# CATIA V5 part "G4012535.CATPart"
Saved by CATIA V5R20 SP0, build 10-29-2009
Part number: G4012535
Revision: 4
Definition: design
Nomenclature: G4012535
Source: made
Description: NOT SPECIFIED
Bounding box of the stored display mesh (mm): x 0 to 35, y -17.817 to 17.817, z -18 to 18
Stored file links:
  C:\Users\Raffaele\Desktop\3D X SITO CF\BOLEX\25-BUSH REF 401\G4012535.CATPart
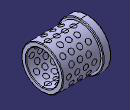
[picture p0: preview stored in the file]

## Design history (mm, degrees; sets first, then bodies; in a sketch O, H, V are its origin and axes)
Body1 "MANIFOLD_SOLID_BREP #8147" (main body)
  Solid1: solid without history
Body2 "MANIFOLD_SOLID_BREP #8294"
  Solid2: solid without history
Body3 "MANIFOLD_SOLID_BREP #8441"
  Solid3: solid without history
Body4 "MANIFOLD_SOLID_BREP #8588"
  Solid4: solid without history
Body5 "MANIFOLD_SOLID_BREP #8735"
  Solid5: solid without history
Body6 "MANIFOLD_SOLID_BREP #8884"
  Solid6: solid without history
Body7 "MANIFOLD_SOLID_BREP #9033"
  Solid7: solid without history
Body8 "MANIFOLD_SOLID_BREP #9182"
  Solid8: solid without history
Body9 "MANIFOLD_SOLID_BREP #9331"
  Solid9: solid without history
Body10 "MANIFOLD_SOLID_BREP #9480"
  Solid10: solid without history
Body11 "MANIFOLD_SOLID_BREP #9629"
  Solid11: solid without history
Body12 "MANIFOLD_SOLID_BREP #9778"
  Solid12: solid without history
Body13 "MANIFOLD_SOLID_BREP #9927"
  Solid13: solid without history
Body14 "MANIFOLD_SOLID_BREP #10076"
  Solid14: solid without history
Body15 "MANIFOLD_SOLID_BREP #10225"
  Solid15: solid without history
Body16 "MANIFOLD_SOLID_BREP #10374"
  Solid16: solid without history
Body17 "MANIFOLD_SOLID_BREP #10523"
  Solid17: solid without history
Body18 "MANIFOLD_SOLID_BREP #10672"
  Solid18: solid without history
Body19 "MANIFOLD_SOLID_BREP #10821"
  Solid19: solid without history
Body20 "MANIFOLD_SOLID_BREP #10972"
  Solid20: solid without history
Body21 "MANIFOLD_SOLID_BREP #11121"
  Solid21: solid without history
Body22 "MANIFOLD_SOLID_BREP #11270"
  Solid22: solid without history
Body23 "MANIFOLD_SOLID_BREP #11421"
  Solid23: solid without history
Body24 "MANIFOLD_SOLID_BREP #11570"
  Solid24: solid without history
Body25 "MANIFOLD_SOLID_BREP #11719"
  Solid25: solid without history
Body26 "MANIFOLD_SOLID_BREP #11868"
  Solid26: solid without history
Body27 "MANIFOLD_SOLID_BREP #12017"
  Solid27: solid without history
Body28 "MANIFOLD_SOLID_BREP #12166"
  Solid28: solid without history
Body29 "MANIFOLD_SOLID_BREP #12315"
  Solid29: solid without history
Body30 "MANIFOLD_SOLID_BREP #12464"
  Solid30: solid without history
Body31 "MANIFOLD_SOLID_BREP #12613"
  Solid31: solid without history
Body32 "MANIFOLD_SOLID_BREP #12760"
  Solid32: solid without history
Body33 "MANIFOLD_SOLID_BREP #12907"
  Solid33: solid without history
Body34 "MANIFOLD_SOLID_BREP #13056"
  Solid34: solid without history
Body35 "MANIFOLD_SOLID_BREP #13205"
  Solid35: solid without history
Body36 "MANIFOLD_SOLID_BREP #13356"
  Solid36: solid without history
Body37 "MANIFOLD_SOLID_BREP #13505"
  Solid37: solid without history
Body38 "MANIFOLD_SOLID_BREP #13654"
  Solid38: solid without history
Body39 "MANIFOLD_SOLID_BREP #13805"
  Solid39: solid without history
Body40 "MANIFOLD_SOLID_BREP #13954"
  Solid40: solid without history
Body41 "MANIFOLD_SOLID_BREP #14103"
  Solid41: solid without history
Body42 "MANIFOLD_SOLID_BREP #14252"
  Solid42: solid without history
Body43 "MANIFOLD_SOLID_BREP #14401"
  Solid43: solid without history
Body44 "MANIFOLD_SOLID_BREP #14550"
  Solid44: solid without history
Body45 "MANIFOLD_SOLID_BREP #14699"
  Solid45: solid without history
Body46 "MANIFOLD_SOLID_BREP #14848"
  Solid46: solid without history
Body47 "MANIFOLD_SOLID_BREP #14997"
  Solid47: solid without history
Body48 "MANIFOLD_SOLID_BREP #15144"
  Solid48: solid without history
Body49 "MANIFOLD_SOLID_BREP #15291"
  Solid49: solid without history
Body50 "MANIFOLD_SOLID_BREP #15440"
  Solid50: solid without history
Body51 "MANIFOLD_SOLID_BREP #15589"
  Solid51: solid without history
Body52 "MANIFOLD_SOLID_BREP #15740"
  Solid52: solid without history
Body53 "MANIFOLD_SOLID_BREP #15889"
  Solid53: solid without history
Body54 "MANIFOLD_SOLID_BREP #16038"
  Solid54: solid without history
Body55 "MANIFOLD_SOLID_BREP #16189"
  Solid55: solid without history
Body56 "MANIFOLD_SOLID_BREP #16338"
  Solid56: solid without history
Body57 "MANIFOLD_SOLID_BREP #16487"
  Solid57: solid without history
